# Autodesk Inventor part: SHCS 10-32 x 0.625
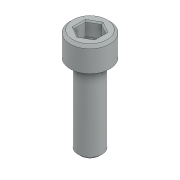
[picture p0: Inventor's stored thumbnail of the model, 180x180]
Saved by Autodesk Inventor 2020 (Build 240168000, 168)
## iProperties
Created: 2020-01
Part Number: SHCS 10-32 x 0.625
Material: Steel, Alloy
Document SubType Name: Modeling
Designer: woodk
Density: 7.73 g/cm^3
Appearance: Semi-Polished
Vendor: KoP
Mass: 3.63646 g
Surface Area: 4.7566 cm^2
Volume: 0.470435 cm^3
Author: woodk
Revision Number: ANY
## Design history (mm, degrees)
feature "Imported1"
body "Solid1"
